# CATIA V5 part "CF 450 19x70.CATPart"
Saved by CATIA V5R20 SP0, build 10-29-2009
Part number: CF 450 19x70
Definition: NONE
Nomenclature: CF 450 19x70
Source: Unknown
Description: CF 450 19x70
Bounding box of the stored display mesh (mm): x -17 to 17, y 0 to 70, z -17 to 17
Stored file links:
  C:\Users\Utente\Desktop\IO LAVORO\3D X SITO CF\X SITO\CF 450\CF 450 19x70.CATPart
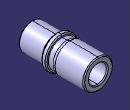
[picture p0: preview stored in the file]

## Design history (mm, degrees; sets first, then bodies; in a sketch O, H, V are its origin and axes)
Body1 "CF 450 19x70" (main body)
  Solid1: solid without history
